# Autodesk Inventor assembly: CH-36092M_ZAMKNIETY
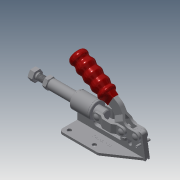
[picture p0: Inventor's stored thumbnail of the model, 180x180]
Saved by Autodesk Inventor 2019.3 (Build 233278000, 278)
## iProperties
Company: Î¢ÈíÖÐ¹ú
Created: 2012-09
Part Number: CH-36092M_ZAMKNIETY
Material: Ogólny
Description: STEP AP203
Document SubType Name: Assembly
Designer: CADENGINEERING4
Sending System: SolidWorks 2010
Preprocessor: SwSTEP 2.0
Title: CH-36092M.STEP
Author: Î¢ÈíÓÃ»§
Revision Number: ÈÎºÎ
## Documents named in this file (14)
- D:\Vault_2016\Projekty\STRONA\Push-pull clamp\CH-36092M\CH-36092M_ZAMKNIETY.iam
- D:\Vault_2016\Projekty\STRONA\Push-pull clamp\CH-36092M\CH-36092-11.ipt
- D:\Vault_2016\Projekty\STRONA\Push-pull clamp\CH-36092M\CH-36092-09.ipt
- D:\Vault_2016\Projekty\STRONA\Push-pull clamp\CH-36092M\CH-SA-085012 SPINDLE SUPPLIED.ipt
- D:\Vault_2016\Projekty\STRONA\Push-pull clamp\CH-36092M\CH-36092-05 LEAD SET.ipt
- D:\Vault_2016\Projekty\STRONA\Push-pull clamp\CH-36092M\CH-36092-01 BASE.ipt
- D:\Vault_2016\Projekty\STRONA\Push-pull clamp\CH-36092M\CH-302-FM-09.ipt
- D:\Vault_2016\Projekty\STRONA\Push-pull clamp\CH-36092M\CH-36092-04 CONNECTING-PLATE.ipt
- D:\Vault_2016\Projekty\STRONA\Push-pull clamp\CH-36092M\CH-36092-07.ipt
- D:\Vault_2016\Projekty\STRONA\Push-pull clamp\CH-36092M\M8 Nut.ipt
- D:\Vault_2016\Projekty\STRONA\Push-pull clamp\CH-36092M\CH-36092-03 HANDLE.ipt
- D:\Vault_2016\Projekty\STRONA\Push-pull clamp\CH-36092M\CH-36092-10.ipt
- D:\Vault_2016\Projekty\STRONA\Push-pull clamp\CH-36092M\CH-36092-02 CREST STALK .ipt
- D:\Vault_2016\Projekty\STRONA\Push-pull clamp\CH-36092M\CH-36092-06.ipt
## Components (15 placed, 15 different names)
1. CH-36092-11_1
2. CH-36092-09_2
3. CH-SA-085012 SPINDLE SUPPLIED_3
4. CH-36092-05 LEAD SET_4
5. CH-36092-01 BASE_5
6. CH-302-FM-09_6
7. CH-36092-04 CONNECTING-PLATE_7
8. CH-36092-07_8
9. M8 Nut_9
10. CH-36092-07_10
11. CH-36092-03 HANDLE_11
12. CH-36092-10_12
13. CH-36092-02 CREST STALK _13
14. CH-36092-04 CONNECTING-PLATE_14
15. CH-36092-06_15
